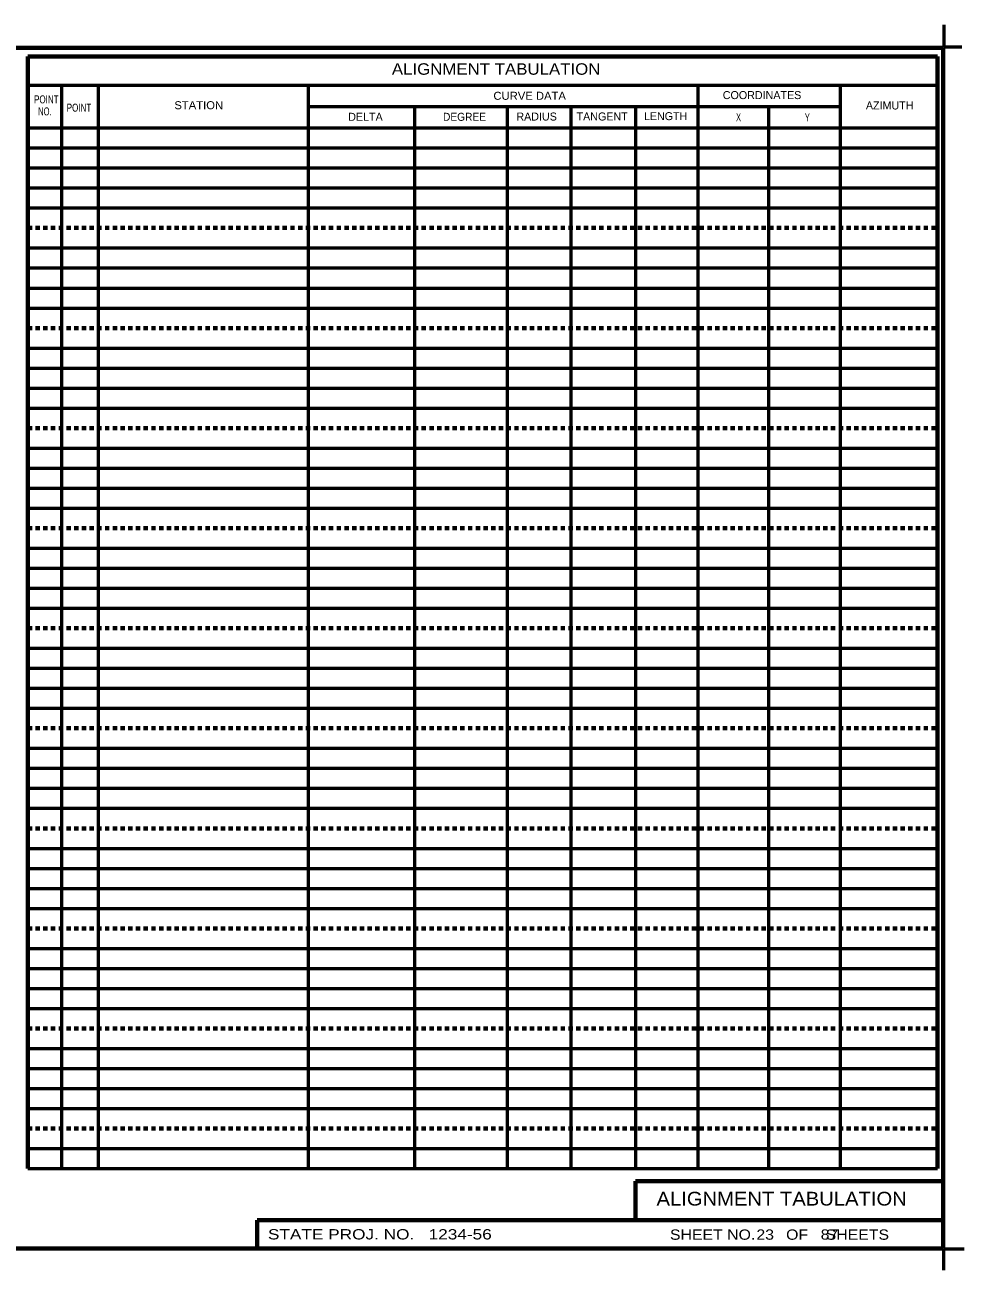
# Model space of a CAD drawing. Extents: x 22753 to 24440, y 5712 to 6801.
# Drawn here: x 23619 to 24440, y 5712 to 6801 of the extents above; entities that cross this region are included whole.
import ezdxf
from ezdxf.enums import TextEntityAlignment as Align

# ---------------------------------------------------------------- set-up
doc = ezdxf.new("R2010")
doc.units = 0
doc.header["$LTSCALE"] = 2.5
doc.linetypes.add('SHORT_DASHED', pattern=[2.7, 1.5, -1.2])
doc.layers.add('27', color=7, linetype='Continuous', lineweight=53)
doc.layers.add('63', color=7, linetype='Continuous', lineweight=70)
doc.layers.add('3', color=7, linetype='Continuous')
doc.layers.add('57', color=7, linetype='Continuous')

msp = doc.modelspace()

# ---------------------------------------------------------------- linework, layer by layer
at = {"layer": '27', "lineweight": 70}
for p, q in [((23621.896, 6773.426), (24416.896, 6773.426)), ((24416.896, 6773.426), (24416.896, 5800.976))]:
    msp.add_line(p, q, dxfattribs=at)
at = {"layer": '27'}
for p, q in [((23621.896, 6748.376), (24416.896, 6748.376)), ((23651.446, 6747.026), (23651.446, 5800.976)), ((23683.346, 6747.376), (23683.346, 5800.976)), ((23867.096, 6747.676), (23867.096, 5800.976)), ((24207.496, 6748.476), (24207.496, 5800.976)), ((24331.896, 6748.376), (24331.896, 5800.976)), ((23867.096, 6729.726), (24331.896, 6729.726)), ((23959.946, 6729.726), (23959.946, 5800.976)), ((24040.846, 6729.726), (24040.846, 5800.976)), ((24096.646, 6729.726), (24096.646, 5800.976)), ((24153.096, 6729.726), (24153.096, 5800.976)), ((24269.196, 6729.726), (24269.196, 5800.976)), ((23621.896, 6710.976), (24416.896, 6710.976)), ((23621.896, 6693.476), (24416.896, 6693.476)), ((23621.896, 6675.976), (24416.896, 6675.976)), ((23621.896, 6658.476), (24416.896, 6658.476)), ((23621.896, 6658.476), (24416.896, 6658.476)), ((23621.896, 6640.976), (24416.896, 6640.976)), ((23621.896, 6605.976), (24416.896, 6605.976)), ((23621.896, 6588.476), (24416.896, 6588.476)), ((23621.896, 6570.976), (24416.896, 6570.976)), ((23621.896, 6553.476), (24416.896, 6553.476)), ((23621.896, 6518.476), (24416.896, 6518.476)), ((23621.896, 6500.976), (24416.896, 6500.976)), ((23621.896, 6483.476), (24416.896, 6483.476)), ((23621.896, 6465.976), (24416.896, 6465.976)), ((23621.896, 6430.976), (24416.896, 6430.976)), ((23621.896, 6413.476), (24416.896, 6413.476)), ((23621.896, 6395.976), (24416.896, 6395.976)), ((23621.896, 6378.476), (24416.896, 6378.476)), ((23621.896, 6343.476), (24416.896, 6343.476)), ((23621.896, 6325.976), (24416.896, 6325.976)), ((23621.896, 6308.476), (24416.896, 6308.476)), ((23621.896, 6290.976), (24416.896, 6290.976)), ((23621.896, 6255.976), (24416.896, 6255.976)), ((23621.896, 6238.476), (24416.896, 6238.476)), ((23621.896, 6220.976), (24416.896, 6220.976)), ((23621.896, 6203.476), (24416.896, 6203.476)), ((23621.896, 6168.476), (24416.896, 6168.476)), ((23621.896, 6150.976), (24416.896, 6150.976)), ((23621.896, 6133.476), (24416.896, 6133.476)), ((23621.896, 6115.976), (24416.896, 6115.976)), ((23621.896, 6080.976), (24416.896, 6080.976)), ((23621.896, 6063.476), (24416.896, 6063.476)), ((23621.896, 6045.976), (24416.896, 6045.976)), ((23621.896, 6028.476), (24416.896, 6028.476)), ((23621.896, 5993.476), (24416.896, 5993.476)), ((23621.896, 5975.976), (24416.896, 5975.976)), ((23621.896, 5958.476), (24416.896, 5958.476)), ((23621.896, 5940.976), (24416.896, 5940.976)), ((23621.896, 5905.976), (24416.896, 5905.976)), ((23621.896, 5888.476), (24416.896, 5888.476)), ((23621.896, 5870.976), (24416.896, 5870.976)), ((23621.896, 5853.476), (24416.896, 5853.476)), ((23621.896, 5818.476), (24416.896, 5818.476)), ((23621.896, 5800.976), (24416.896, 5800.976))]:
    msp.add_line(p, q, dxfattribs=at)
at = {"layer": '27', "linetype": 'SHORT_DASHED', "lineweight": 70}
for p, q in [((23621.896, 6623.476), (24416.896, 6623.476)), ((23621.896, 6535.976), (24416.896, 6535.976)), ((23621.896, 6448.476), (24416.896, 6448.476)), ((23621.896, 6360.976), (24416.896, 6360.976)), ((23621.896, 6273.476), (24416.896, 6273.476)), ((23621.896, 6185.976), (24416.896, 6185.976)), ((23621.896, 6098.476), (24416.896, 6098.476)), ((23621.896, 6010.976), (24416.896, 6010.976)), ((23621.896, 5923.476), (24416.896, 5923.476)), ((23621.896, 5835.976), (24416.896, 5835.976))]:
    msp.add_line(p, q, dxfattribs=at)
at = {"layer": '63', "lineweight": 53}
for p, q in [((24422.396, 6801.055), (24422.396, 6781.476)), ((24438.144, 6781.476), (24422.396, 6781.476)), ((24422.396, 5712.174), (24422.396, 5730.476)), ((24440.217, 5730.476), (24422.396, 5730.476))]:
    msp.add_line(p, q, dxfattribs=at)
at = {"layer": '63'}
for p, q in [((22816.896, 6780.976), (24421.896, 6780.976)), ((23621.896, 5800.976), (23621.896, 6773.426)), ((24421.896, 5730.976), (24421.896, 6780.976)), ((24153.096, 5789.896), (24421.896, 5789.896)), ((24153.096, 5755.976), (24153.096, 5789.896)), ((23822.396, 5730.976), (23822.396, 5755.976)), ((23822.396, 5755.976), (24421.896, 5755.976)), ((22816.896, 5730.976), (24421.896, 5730.976))]:
    msp.add_line(p, q, dxfattribs=at)

# ---------------------------------------------------------------- texts
at = {"layer": '27', "width": 0.75}
for p in [(23638.117, 6732.423), (23666.66, 6725.176)]:
    msp.add_text('POINT', height=7, dxfattribs=at).set_placement(p, align=Align.CENTER)
at = {"layer": '27', "width": 0.65}
msp.add_text('NO.', height=7, dxfattribs=at).set_placement((23630.996, 6721.926))
at = {"layer": '3', "width": 1.1}
msp.add_text('ALIGNMENT TABULATION ', height=12, dxfattribs=at).set_placement((24171.413, 5768.62))
at = {"layer": '57'}
for s, height, width, p in [('ALIGNMENT TABULATION', 10, 1.1, (24031.237, 6757.476)), ('CURVE DATA', 7, 1.05, (24060.553, 6735.576)), ('STATION', 7, 1.05, (23771.309, 6727.326)), ('DEGREE', 7, 0.95, (24003.6, 6717.176))]:
    msp.add_text(s, height=height, dxfattribs=dict(at, width=width)).set_placement(p, align=Align.CENTER)
for s, p in [('COORDINATES', (24263.645, 6736.176)), ('AZIMUTH', (24375.192, 6727.126)), ('DELTA', (23917.041, 6717.176)), ('RADIUS', (24066.599, 6717.426)), ('TANGENT', (24123.881, 6717.476))]:
    msp.add_text(s, height=7, dxfattribs=at).set_placement(p, align=Align.CENTER)
msp.add_text('LENGTH', height=6.95, dxfattribs=at).set_placement((24198.183, 6717.776), align=Align.RIGHT)
at = {"layer": '57', "width": 0.7}
for s, p in [('X', (24245.248, 6716.801)), ('Y', (24305.384, 6716.666))]:
    msp.add_text(s, height=6.95, dxfattribs=at).set_placement(p, align=Align.RIGHT)
at = {"layer": '63'}
for s, width, p in [('STATE PROJ. NO.   1234-56               ', 1.25, (23831.796, 5738.976)), ('SHEET NO.       OF    SHEETS', 1.15, (24183.155, 5738.697)), ('23 ', 1.15, (24258.696, 5738.726)), ('87 ', 1.15, (24314.896, 5738.776))]:
    msp.add_text(s, height=9, dxfattribs=dict(at, width=width)).set_placement(p)

doc.saveas('drawing.dxf')
